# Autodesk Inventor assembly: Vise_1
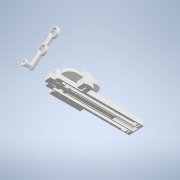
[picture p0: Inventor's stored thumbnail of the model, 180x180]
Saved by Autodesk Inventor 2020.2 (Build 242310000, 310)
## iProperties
Created: 2019-12
Part Number: Vise_1
Document SubType Name: Assembly
Designer: Patrick Everitt
Author: Patrick Everitt
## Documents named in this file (18)
- C:\Users\Patrick Everitt\Documents\Inventor\Fire_Vise\Vise_1.iam
- C:\Users\Patrick Everitt\Documents\Inventor\Fire_Vise\Big_Tube.ipt
- C:\Users\Patrick Everitt\Documents\Inventor\Fire_Vise\Small_Tube.ipt
- C:\Users\Patrick Everitt\Documents\Inventor\Fire_Vise\Fixed_Left.ipt
- C:\Users\Patrick Everitt\Documents\Inventor\Fire_Vise\Fixed_Right.ipt
- C:\Users\Patrick Everitt\Documents\Inventor\Fire_Vise\Movable_Right.ipt
- C:\Users\Patrick Everitt\Documents\Inventor\Fire_Vise\Jaw_Backup.ipt
- C:\Users\Patrick Everitt\Documents\Inventor\Fire_Vise\Jaw_Insert.ipt
- C:\Users\Patrick Everitt\Documents\Inventor\Fire_Vise\Front_Cover.ipt
- C:\Users\Patrick Everitt\Documents\Inventor\Fire_Vise\Screw.ipt
- C:\Users\Patrick Everitt\Documents\Inventor\Fire_Vise\Acme_Nut.ipt
- C:\Users\Patrick Everitt\Documents\Inventor\Fire_Vise\Nut_Sub_Assy.iam
- C:\Users\Patrick Everitt\Documents\Inventor\Fire_Vise\Base.ipt
- C:\Users\Patrick Everitt\Documents\Inventor\Fire_Vise\Bolt_Plate_Rear.ipt
- C:\Users\Patrick Everitt\Documents\Inventor\Fire_Vise\Movable_Left.ipt
- C:\Users\Patrick Everitt\Documents\Inventor\Fire_Vise\Screw_Stop.ipt
- C:\Users\Patrick Everitt\Documents\Inventor\Fire_Vise\Cover_Back.ipt
- C:\Users\Patrick Everitt\Documents\Inventor\Fire_Vise\wrench.iam
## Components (20 placed, 17 different names)
1. Big_Tube:1 — Mate:1, Mate:2, Mate:3, Flush:1, Flush:2, Mate:20, Mate:21, Mate:22, Mate:23, Flush:15, Flush:16, Mate:24, Mate:25, Mate:26, Mate:27, Flush:17
2. Cover_Back:1 — Mate:33, Mate:34, Mate:35
3. Screw_Stop:1 — Mate:31, Mate:32
4. Movable_Left:1 — Flush:18, Flush:19, Mate:28
5. Bolt_Plate_Rear:1 — Mate:26, Mate:27, Flush:17
6. Base:1 — Mate:24, Mate:25, Mate:30
7. Nut_Sub_Assy:1 [sub-assembly] — Mate:20, Mate:21, Mate:22, Mate:29, Mate:32, Mate:33, Mate:34, Mate:35
8. Acme_Nut:1 — Mate:18, Mate:19
9. Screw:1 — Mate:16, Mate:17, Mate:18, Mate:29, Mate:31, Mate:37, Mate:38
10. Small_Tube:1 — Mate:1, Mate:2, Mate:6, Flush:7, Flush:8, Flush:18, Flush:19, Mate:28, Flush:20, Mate:36
11. Fixed_Left:1 — Mate:3, Flush:1, Flush:16, Mate:30
12. Fixed_Right:1 — Flush:2, Flush:9, Mate:7, Mate:8, Mate:23, Flush:15
13. Movable_Right:2 — Mate:6, Flush:7, Flush:8, Flush:10, Mate:9, Mate:10
14. Jaw_Insert:1 — Mate:13, Mate:14, Flush:12
15. Jaw_Backup:1 — Flush:9, Mate:7, Mate:8, Mate:13, Mate:14, Flush:12
16. Jaw_Backup:2 — Flush:10, Mate:9, Mate:10, Mate:11, Mate:12, Flush:11
17. Jaw_Insert:2 — Mate:11, Mate:12, Flush:11
18. Front_Cover:1 — Mate:16, Mate:17, Mate:19, Flush:20, Mate:36
19. Screw_Stop:2 — Mate:37, Mate:38
20. wrench:1 [sub-assembly]
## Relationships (49: Mate 35, Flush 14)
- Mate:1: Big_Tube:1 ↔ Small_Tube:1
- Mate:2: Big_Tube:1 ↔ Small_Tube:1
- Mate:3: Big_Tube:1 ↔ Fixed_Left:1
- Flush:1: Big_Tube:1 ↔ Fixed_Left:1
- Flush:2: Big_Tube:1 ↔ Fixed_Right:1
- Mate:6: Small_Tube:1 ↔ Movable_Right:2
- Flush:7: Small_Tube:1 ↔ Movable_Right:2
- Flush:8: Small_Tube:1 ↔ Movable_Right:2
- Flush:9: Fixed_Right:1 ↔ Jaw_Backup:1
- Mate:7: Fixed_Right:1 ↔ Jaw_Backup:1
- Mate:8: Fixed_Right:1 ↔ Jaw_Backup:1
- Flush:10: Movable_Right:2 ↔ Jaw_Backup:2
- Mate:9: Movable_Right:2 ↔ Jaw_Backup:2
- Mate:10: Movable_Right:2 ↔ Jaw_Backup:2
- Mate:11: Jaw_Backup:2 ↔ Jaw_Insert:2
- Mate:12: Jaw_Backup:2 ↔ Jaw_Insert:2
- Flush:11: Jaw_Backup:2 ↔ Jaw_Insert:2
- Mate:13: Jaw_Insert:1 ↔ Jaw_Backup:1
- Mate:14: Jaw_Insert:1 ↔ Jaw_Backup:1
- Flush:12: Jaw_Insert:1 ↔ Jaw_Backup:1
- Mate:16: Screw:1 ↔ Front_Cover:1
- Mate:17: Screw:1 ↔ Front_Cover:1
- Mate:18: Acme_Nut:1 ↔ Screw:1
- Mate:19: Acme_Nut:1 ↔ Front_Cover:1
- Mate:20: Big_Tube:1 ↔ Nut_Sub_Assy:1
- Mate:21: Big_Tube:1 ↔ Nut_Sub_Assy:1
- Mate:22: Big_Tube:1 ↔ Nut_Sub_Assy:1
- Mate:23: Big_Tube:1 ↔ Fixed_Right:1
- Flush:15: Big_Tube:1 ↔ Fixed_Right:1
- Flush:16: Big_Tube:1 ↔ Fixed_Left:1
- Mate:24: Big_Tube:1 ↔ Base:1
- Mate:25: Big_Tube:1 ↔ Base:1
- Mate:26: Big_Tube:1 ↔ Bolt_Plate_Rear:1
- Mate:27: Big_Tube:1 ↔ Bolt_Plate_Rear:1
- Flush:17: Big_Tube:1 ↔ Bolt_Plate_Rear:1
- Flush:18: Movable_Left:1 ↔ Small_Tube:1
- Flush:19: Movable_Left:1 ↔ Small_Tube:1
- Mate:28: Movable_Left:1 ↔ Small_Tube:1
- Mate:29: Nut_Sub_Assy:1 ↔ Screw:1
- Flush:20: Small_Tube:1 ↔ Front_Cover:1
- Mate:30: Base:1 ↔ Fixed_Left:1
- Mate:31: Screw_Stop:1 ↔ Screw:1
- Mate:32: Screw_Stop:1 ↔ Nut_Sub_Assy:1
- Mate:33: Cover_Back:1 ↔ Nut_Sub_Assy:1
- Mate:34: Cover_Back:1 ↔ Nut_Sub_Assy:1
- Mate:35: Cover_Back:1 ↔ Nut_Sub_Assy:1
- Mate:36: Small_Tube:1 ↔ Front_Cover:1
- Mate:37: Screw:1 ↔ Screw_Stop:2
- Mate:38: Screw:1 ↔ Screw_Stop:2
